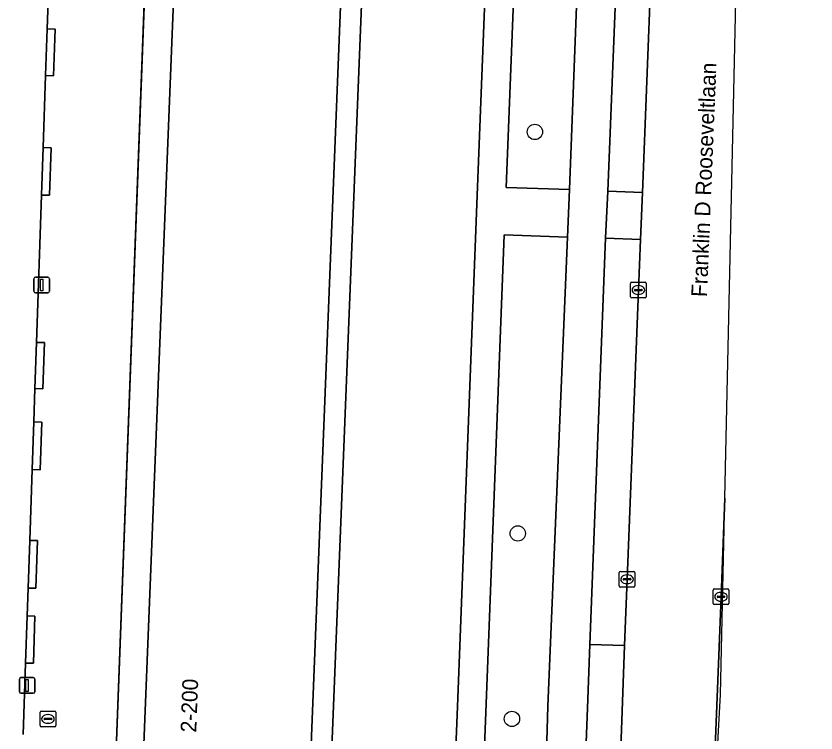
# Model space of a CAD drawing. Extents: x 160786 to 161429, y 386828 to 387485.
# Drawn here: x 161377.2 to 161428.2, y 387309 to 387354.7 of the extents above; entities that cross this region are included whole.
import ezdxf

# ---------------------------------------------------------------- set-up
doc = ezdxf.new("R2010")
doc.units = 0
for name, color, linetype in [('IMGEO_Berm_groen', 7, 'Continuous'), ('IMGEO_Berm_open', 7, 'Continuous'), ('IMGEO_Boom', 7, 'Continuous'), ('IMGEO_Erf', 7, 'Continuous'), ('IMGEO_Fietspad_gesloten', 7, 'Continuous'), ('IMGEO_Groenvoorziening', 7, 'Continuous'), ('IMGEO_Kolk', 7, 'Continuous'), ('IMGEO_Lichtmast', 7, 'Continuous'), ('IMGEO_Openbare_ruimte_label', 7, 'Continuous'), ('IMGEO_Pand', 7, 'Continuous'), ('IMGEO_Pand_nummerreeks', 7, 'Continuous'), ('IMGEO_Pand_overbouw', 7, 'Continuous'), ('IMGEO_Rijbaan_lokaal_gesloten', 7, 'Continuous'), ('IMGEO_Rijbaan_lokaal_open', 7, 'Continuous'), ('IMGEO_Rioolput', 7, 'Continuous'), ('IMGEO_Voetpad_open', 7, 'Continuous')]:
    doc.layers.add(name, color=color, linetype=linetype)

msp = doc.modelspace()

# ---------------------------------------------------------------- linework, layer by layer
at = {"layer": 'IMGEO_Berm_groen'}
for points in [[(161418.124, 387425.095), (161417.984, 387420.162), (161417.456, 387406.756), (161416.95, 387394.647), (161414.908, 387343.546), (161417.126, 387343.449), (161417.667, 387357.66), (161419.182, 387395.472)], [(161410.987, 387408.729), (161408.446, 387343.777), (161412.474, 387343.644), (161414.364, 387393.126), (161415.085, 387409.589)]]:
    msp.add_lwpolyline(points, dxfattribs=at)
for points in [[(161412.336, 387340.617), (161408.308, 387340.766), (161407.158, 387310.893), (161406.779, 387301.147), (161410.82, 387301.106), (161411.099, 387310.744)], [(161416.995, 387340.459), (161414.776, 387340.54), (161413.773, 387314.665), (161415.98, 387314.594), (161416.141, 387318.819), (161416.86, 387337.244)]]:
    msp.add_lwpolyline(points, close=True, dxfattribs=at)
at = {"layer": 'IMGEO_Berm_open'}
msp.add_lwpolyline([(161421.338, 387297.879), (161422.084, 387311.477), (161422.363, 387323.994), (161422.123, 387317.703), (161421.384, 387299.063), (161421.338, 387297.879)], dxfattribs=at)
msp.add_lwpolyline([(161415.779, 387309.226), (161415.98, 387314.594), (161413.773, 387314.665), (161413.611, 387310.602), (161412.945, 387293.071), (161415.15, 387292.986), (161415.39, 387299.413)], close=True, dxfattribs=at)
at = {"layer": 'IMGEO_Boom'}
for centre in [(161410.268, 387347.316), (161409.179, 387321.737), (161408.808, 387309.925)]:
    msp.add_circle(centre, 0.489, dxfattribs=at)
at = {"layer": 'IMGEO_Erf'}
msp.add_lwpolyline([(161389.177, 387404.131), (161387.379, 387404.202), (161387.512, 387407.162), (161387.325, 387407.184), (161386.533, 387386.078), (161383.304, 387300.054), (161382.556, 387283.379), (161382.717, 387283.373), (161384.357, 387283.307)], close=True, dxfattribs=at)
at = {"layer": 'IMGEO_Fietspad_gesloten'}
for points in [[(161412.905, 387290.764), (161412.945, 387293.071), (161413.611, 387310.602), (161413.773, 387314.665), (161414.776, 387340.54), (161414.908, 387343.546), (161416.95, 387394.647), (161417.456, 387406.756), (161417.984, 387420.162), (161418.124, 387425.095)], [(161415.626, 387423.508), (161415.085, 387409.589), (161414.364, 387393.126), (161412.474, 387343.644), (161412.336, 387340.617), (161411.099, 387310.744), (161410.82, 387301.106), (161410.5, 387293.137), (161410.411, 387291.732)]]:
    msp.add_lwpolyline(points, dxfattribs=at)
at = {"layer": 'IMGEO_Groenvoorziening'}
for points in [[(161408.336, 387409.842), (161407.914, 387409.866), (161401.406, 387410.194), (161396.105, 387277.267), (161396.044, 387275.749), (161402.026, 387275.396)], [(161406.614, 387343.82), (161409.164, 387408.93)], [(161404.027, 387277.41), (161404.513, 387290.168), (161405.332, 387310.717), (161406.614, 387343.82)]]:
    msp.add_lwpolyline(points, dxfattribs=at)
at = {"layer": 'IMGEO_Kolk'}
for p, q in [((161416.359, 387336.818), (161416.359, 387337.67)), ((161416.434, 387337.744), (161417.286, 387337.744)), ((161416.847, 387337.524), (161416.872, 387337.524)), ((161417.36, 387337.67), (161417.36, 387336.818)), ((161416.618, 387337.238), (161416.618, 387337.25)), ((161417.056, 387337.201), (161416.658, 387337.201)), ((161416.661, 387337.287), (161417.059, 387337.287)), ((161417.102, 387337.25), (161417.102, 387337.238)), ((161417.286, 387336.744), (161416.434, 387336.744)), ((161416.87, 387336.964), (161416.845, 387336.964)), ((161415.64, 387318.393), (161415.64, 387319.245)), ((161415.715, 387319.319), (161416.567, 387319.319)), ((161416.641, 387319.245), (161416.641, 387318.393)), ((161415.899, 387318.813), (161415.899, 387318.825)), ((161416.337, 387318.776), (161415.939, 387318.776)), ((161415.942, 387318.862), (161416.34, 387318.862)), ((161416.128, 387319.099), (161416.153, 387319.099)), ((161416.383, 387318.825), (161416.383, 387318.813)), ((161416.567, 387318.319), (161415.715, 387318.319)), ((161416.151, 387318.539), (161416.126, 387318.539)), ((161421.697, 387318.203), (161422.549, 387318.203)), ((161421.622, 387317.277), (161421.622, 387318.129)), ((161421.881, 387317.697), (161421.881, 387317.709)), ((161422.319, 387317.66), (161421.921, 387317.66)), ((161421.924, 387317.746), (161422.322, 387317.746)), ((161422.11, 387317.983), (161422.135, 387317.983)), ((161422.365, 387317.709), (161422.365, 387317.697)), ((161422.623, 387318.129), (161422.623, 387317.277)), ((161422.549, 387317.203), (161421.697, 387317.203)), ((161422.133, 387317.423), (161422.108, 387317.423))]:
    msp.add_line(p, q, dxfattribs=at)
for points in [[(161416.359, 387336.818), (161416.359, 387337.67)], [(161416.434, 387337.744), (161417.286, 387337.744)], [(161417.36, 387337.67), (161417.36, 387336.818)], [(161417.286, 387336.744), (161416.434, 387336.744)], [(161415.64, 387318.393), (161415.64, 387319.245)], [(161415.715, 387319.319), (161416.567, 387319.319)], [(161416.641, 387319.245), (161416.641, 387318.393)], [(161416.567, 387318.319), (161415.715, 387318.319)], [(161421.697, 387318.203), (161422.549, 387318.203)], [(161421.622, 387317.277), (161421.622, 387318.129)], [(161422.623, 387318.129), (161422.623, 387317.277)], [(161422.549, 387317.203), (161421.697, 387317.203)]]:
    msp.add_lwpolyline(points, dxfattribs=at)
for centre, radius, start, end in [((161416.436, 387337.668), 0.0765, 91.552, 178.448), ((161416.436, 387337.668), 0.0765, 91.552, 178.448), ((161417.284, 387337.668), 0.0765, 1.552, 88.448), ((161417.284, 387337.668), 0.0765, 1.552, 88.448), ((161416.658, 387337.247), 0.0403, 85.8775, 175.7526), ((161416.655, 387337.237), 0.0366, 178.938, 274.7102), ((161417.059, 387337.244), 0.043, 264.8664, 352.4533), ((161417.063, 387337.249), 0.0386, 1.7309, 96.639), ((161416.436, 387336.82), 0.0765, 181.552, 268.448), ((161416.436, 387336.82), 0.0765, 181.552, 268.448), ((161417.284, 387336.82), 0.0765, 271.552, 358.448), ((161417.284, 387336.82), 0.0765, 271.552, 358.448), ((161415.717, 387319.243), 0.0765, 91.552, 178.448), ((161415.717, 387319.243), 0.0765, 91.552, 178.448), ((161416.565, 387319.243), 0.0765, 1.552, 88.448), ((161416.565, 387319.243), 0.0765, 1.552, 88.448), ((161415.939, 387318.822), 0.0403, 85.8775, 175.7526), ((161415.936, 387318.812), 0.0366, 178.938, 274.7102), ((161416.34, 387318.819), 0.043, 264.8664, 352.4533), ((161416.344, 387318.824), 0.0386, 1.7309, 96.639), ((161415.717, 387318.395), 0.0765, 181.552, 268.448), ((161415.717, 387318.395), 0.0765, 181.552, 268.448), ((161416.565, 387318.395), 0.0765, 271.552, 358.448), ((161416.565, 387318.395), 0.0765, 271.552, 358.448), ((161421.699, 387318.127), 0.0765, 91.552, 178.448), ((161421.699, 387318.127), 0.0765, 91.552, 178.448), ((161422.547, 387318.127), 0.0765, 1.552, 88.448), ((161422.547, 387318.127), 0.0765, 1.552, 88.448), ((161421.921, 387317.706), 0.0403, 85.8775, 175.7526), ((161421.918, 387317.696), 0.0366, 178.938, 274.7102), ((161422.322, 387317.703), 0.043, 264.8664, 352.4533), ((161422.326, 387317.708), 0.0386, 1.7309, 96.639), ((161421.699, 387317.279), 0.0765, 181.552, 268.448), ((161421.699, 387317.279), 0.0765, 181.552, 268.448), ((161422.547, 387317.279), 0.0765, 271.552, 358.448), ((161422.547, 387317.279), 0.0765, 271.552, 358.448)]:
    msp.add_arc(centre, radius, start, end, dxfattribs=at)
for centre, major_axis, ratio, start_param, end_param in [((161416.846, 387337.244), (-0.387, 0.002), 0.722429, 4.712389, 7.853982), ((161416.871, 387337.244), (-0.39, 0.002), 0.717154, 1.570796, 4.712389), ((161416.127, 387318.819), (-0.387, 0.002), 0.722429, 4.712389, 7.853982), ((161416.152, 387318.819), (-0.39, 0.002), 0.717154, 1.570796, 4.712389), ((161422.109, 387317.703), (-0.387, 0.002), 0.722429, 4.712389, 7.853982), ((161422.134, 387317.703), (-0.39, 0.002), 0.717154, 1.570796, 4.712389)]:
    msp.add_ellipse(centre, major_axis=major_axis, ratio=ratio, start_param=start_param, end_param=end_param, dxfattribs=at)
at = {"layer": 'IMGEO_Lichtmast'}
for p, q in [((161378.457, 387338.068), (161379.247, 387338.068)), ((161379.247, 387338.068), (161378.457, 387338.068)), ((161378.357, 387337.168), (161378.357, 387337.968)), ((161378.357, 387337.968), (161378.357, 387337.168)), ((161379.347, 387337.968), (161379.347, 387337.168)), ((161379.347, 387337.168), (161379.347, 387337.968)), ((161379.247, 387337.068), (161378.457, 387337.068)), ((161378.457, 387337.068), (161379.247, 387337.068)), ((161377.531, 387312.553), (161378.321, 387312.553)), ((161378.321, 387312.553), (161377.531, 387312.553)), ((161377.431, 387311.653), (161377.431, 387312.453)), ((161377.431, 387312.453), (161377.431, 387311.653)), ((161378.421, 387312.453), (161378.421, 387311.653)), ((161378.421, 387311.653), (161378.421, 387312.453)), ((161378.321, 387311.553), (161377.531, 387311.553)), ((161377.531, 387311.553), (161378.321, 387311.553))]:
    msp.add_line(p, q, dxfattribs=at)
for points in [[(161378.777, 387337.943), (161378.927, 387337.943), (161378.927, 387337.193), (161378.777, 387337.193), (161378.777, 387337.943)], [(161377.851, 387312.428), (161378.001, 387312.428), (161378.001, 387311.678), (161377.851, 387311.678), (161377.851, 387312.428)]]:
    msp.add_lwpolyline(points, dxfattribs=at)
for centre, start, end in [((161378.457, 387337.968), 90, 180), ((161378.457, 387337.968), 90, 180), ((161379.247, 387337.968), 0, 90), ((161379.247, 387337.968), 360, 90), ((161378.457, 387337.168), 180, 270), ((161378.457, 387337.168), 180, 270), ((161379.247, 387337.168), 270, 0), ((161379.247, 387337.168), 270, 0), ((161377.531, 387312.453), 90, 180), ((161377.531, 387312.453), 90, 180), ((161378.321, 387312.453), 0, 90), ((161378.321, 387312.453), 360, 90), ((161377.531, 387311.653), 180, 270), ((161377.531, 387311.653), 180, 270), ((161378.321, 387311.653), 270, 0), ((161378.321, 387311.653), 270, 0)]:
    msp.add_arc(centre, 0.1, start, end, dxfattribs=at)
at = {"layer": 'IMGEO_Pand'}
msp.add_lwpolyline([(161387.466, 387410.734), (161387.325, 387407.184), (161387.512, 387407.162), (161387.379, 387404.202), (161389.177, 387404.131), (161384.357, 387283.307), (161382.717, 387283.373), (161382.556, 387283.379), (161377.355, 387283.586), (161377.217, 387280.125), (161387.248, 387279.724), (161388.167, 387279.687), (161393.513, 387279.474), (161394.362, 387279.44), (161394.861, 387279.42), (161399.828, 387403.974), (161399.325, 387403.994), (161398.105, 387404.043), (161395.161, 387404.16), (161395.41, 387410.418)], close=True, dxfattribs=at)
at = {"layer": 'IMGEO_Pand_overbouw'}
msp.add_lwpolyline([(161382.556, 387283.379), (161382.717, 387283.373), (161384.357, 387283.307), (161389.177, 387404.131), (161387.379, 387404.202), (161387.512, 387407.162), (161387.325, 387407.184), (161383.304, 387300.054)], close=True, dxfattribs=at)
at = {"layer": 'IMGEO_Rijbaan_lokaal_gesloten'}
for points in [[(161407.62, 387092.708), (161414.633, 387175.718), (161419.75, 387268.949), (161421.338, 387297.879), (161421.384, 387299.063), (161422.123, 387317.703), (161422.363, 387323.994), (161424.054, 387399.845), (161428.174, 387449.614), (161425.941, 387449.697), (161425.82, 387446.281), (161425.787, 387444.766)], [(161420.236, 387423.327), (161420.186, 387421.638), (161419.965, 387412.467), (161419.262, 387397.687), (161419.182, 387395.472), (161417.667, 387357.66), (161417.126, 387343.449), (161416.995, 387340.459), (161416.86, 387337.244), (161416.141, 387318.819), (161415.98, 387314.594), (161415.779, 387309.226), (161415.39, 387299.413), (161415.15, 387292.986), (161414.772, 387284.025), (161414.515, 387277.789)]]:
    msp.add_lwpolyline(points, dxfattribs=at)
at = {"layer": 'IMGEO_Rijbaan_lokaal_open'}
msp.add_lwpolyline([(161377.667, 387308.937), (161377.823, 387313.485), (161377.926, 387316.495), (161377.987, 387318.261), (161378.091, 387321.296), (161378.246, 387325.817), (161378.35, 387328.854), (161378.423, 387330.962), (161378.524, 387333.909), (161378.846, 387343.297), (161378.949, 387346.319), (161379.106, 387350.904), (161379.208, 387353.876), (161379.269, 387355.642), (161379.373, 387358.677), (161379.54, 387363.212), (161379.661, 387366.283), (161379.745, 387368.392), (161379.86, 387371.325), (161380.041, 387375.91), (161380.158, 387378.87), (161380.227, 387380.624), (161380.347, 387383.659)], dxfattribs=at)
at = {"layer": 'IMGEO_Rioolput'}
for p, q in [((161378.751, 387309.497), (161378.751, 387310.349)), ((161378.826, 387310.423), (161379.678, 387310.423)), ((161379.239, 387310.203), (161379.264, 387310.203)), ((161379.752, 387310.349), (161379.752, 387309.497)), ((161379.01, 387309.917), (161379.01, 387309.929)), ((161379.448, 387309.88), (161379.05, 387309.88)), ((161379.053, 387309.966), (161379.451, 387309.966)), ((161379.262, 387309.643), (161379.237, 387309.643)), ((161379.494, 387309.929), (161379.494, 387309.917)), ((161379.678, 387309.423), (161378.826, 387309.423))]:
    msp.add_line(p, q, dxfattribs=at)
for points in [[(161378.751, 387309.497), (161378.751, 387310.349)], [(161378.826, 387310.423), (161379.678, 387310.423)], [(161379.752, 387310.349), (161379.752, 387309.497)], [(161379.678, 387309.423), (161378.826, 387309.423)]]:
    msp.add_lwpolyline(points, dxfattribs=at)
for centre, radius, start, end in [((161378.828, 387310.347), 0.0765, 91.552, 178.448), ((161378.828, 387310.347), 0.0765, 91.552, 178.448), ((161379.676, 387310.347), 0.0765, 1.552, 88.448), ((161379.676, 387310.347), 0.0765, 1.552, 88.448), ((161378.828, 387309.499), 0.0765, 181.552, 268.448), ((161378.828, 387309.499), 0.0765, 181.552, 268.448), ((161379.05, 387309.926), 0.0403, 85.8775, 175.7526), ((161379.047, 387309.916), 0.0366, 178.938, 274.7102), ((161379.451, 387309.923), 0.043, 264.8664, 352.4533), ((161379.455, 387309.928), 0.0386, 1.7309, 96.639), ((161379.676, 387309.499), 0.0765, 271.552, 358.448), ((161379.676, 387309.499), 0.0765, 271.552, 358.448)]:
    msp.add_arc(centre, radius, start, end, dxfattribs=at)
for centre, major_axis, ratio, start_param, end_param in [((161379.238, 387309.923), (-0.387, 0.002), 0.722429, 4.712389, 7.853982), ((161379.263, 387309.923), (-0.39, 0.002), 0.717154, 1.570796, 4.712389)]:
    msp.add_ellipse(centre, major_axis=major_axis, ratio=ratio, start_param=start_param, end_param=end_param, dxfattribs=at)
at = {"layer": 'IMGEO_Voetpad_open'}
for points in [[(161401.406, 387410.194), (161399.558, 387410.263), (161399.325, 387403.994), (161399.828, 387403.974), (161394.861, 387279.42), (161394.362, 387279.44), (161394.27, 387277.128), (161394.265, 387276.953), (161394.59, 387276.996), (161395.087, 387277.074), (161395.601, 387277.168), (161395.905, 387277.242), (161396.105, 387277.267)], [(161379.106, 387350.904), (161379.608, 387350.889), (161379.709, 387353.861), (161379.208, 387353.876)], [(161378.846, 387343.297), (161379.349, 387343.282), (161379.452, 387346.304), (161378.949, 387346.319)], [(161417.126, 387343.449), (161414.908, 387343.546), (161414.776, 387340.54), (161416.995, 387340.459)], [(161378.524, 387333.909), (161378.423, 387330.962), (161378.925, 387330.947), (161379.027, 387333.894)], [(161378.246, 387325.817), (161378.748, 387325.801), (161378.853, 387328.838), (161378.35, 387328.854)], [(161378.091, 387321.296), (161377.987, 387318.261), (161378.488, 387318.246), (161378.593, 387321.281)], [(161377.823, 387313.485), (161378.324, 387313.469), (161378.427, 387316.479), (161377.926, 387316.495)]]:
    msp.add_lwpolyline(points, close=True, dxfattribs=at)
for points in [[(161409.164, 387408.93), (161406.614, 387343.82), (161405.332, 387310.717), (161404.513, 387290.168), (161404.027, 387277.41)], [(161405.792, 387276.211), (161406.451, 387293.297), (161410.5, 387293.137), (161410.82, 387301.106), (161406.779, 387301.147), (161407.158, 387310.893), (161408.308, 387340.766), (161412.336, 387340.617), (161412.474, 387343.644), (161408.446, 387343.777), (161410.987, 387408.729)], [(161383.304, 387300.054), (161386.533, 387386.078)], [(161379.269, 387355.642), (161379.208, 387353.876), (161379.709, 387353.861), (161379.608, 387350.889), (161379.106, 387350.904), (161378.949, 387346.319), (161379.452, 387346.304), (161379.349, 387343.282), (161378.846, 387343.297), (161378.524, 387333.909), (161379.027, 387333.894), (161378.925, 387330.947), (161378.423, 387330.962), (161378.35, 387328.854), (161378.853, 387328.838), (161378.748, 387325.801), (161378.246, 387325.817), (161378.091, 387321.296), (161378.593, 387321.281), (161378.488, 387318.246), (161377.987, 387318.261), (161377.926, 387316.495), (161378.427, 387316.479), (161378.324, 387313.469), (161377.823, 387313.485), (161377.667, 387308.937)]]:
    msp.add_lwpolyline(points, dxfattribs=at)

# ---------------------------------------------------------------- texts
at = {"layer": 'IMGEO_Openbare_ruimte_label'}
msp.add_text('Franklin D Rooseveltlaan', height=1, rotation=87.6498, dxfattribs=at).set_placement((161421.225, 387336.785))
at = {"layer": 'IMGEO_Pand_nummerreeks'}
msp.add_text('2-200', height=1, rotation=87.858, dxfattribs=at).set_placement((161388.696, 387309.047))

doc.saveas('drawing.dxf')
